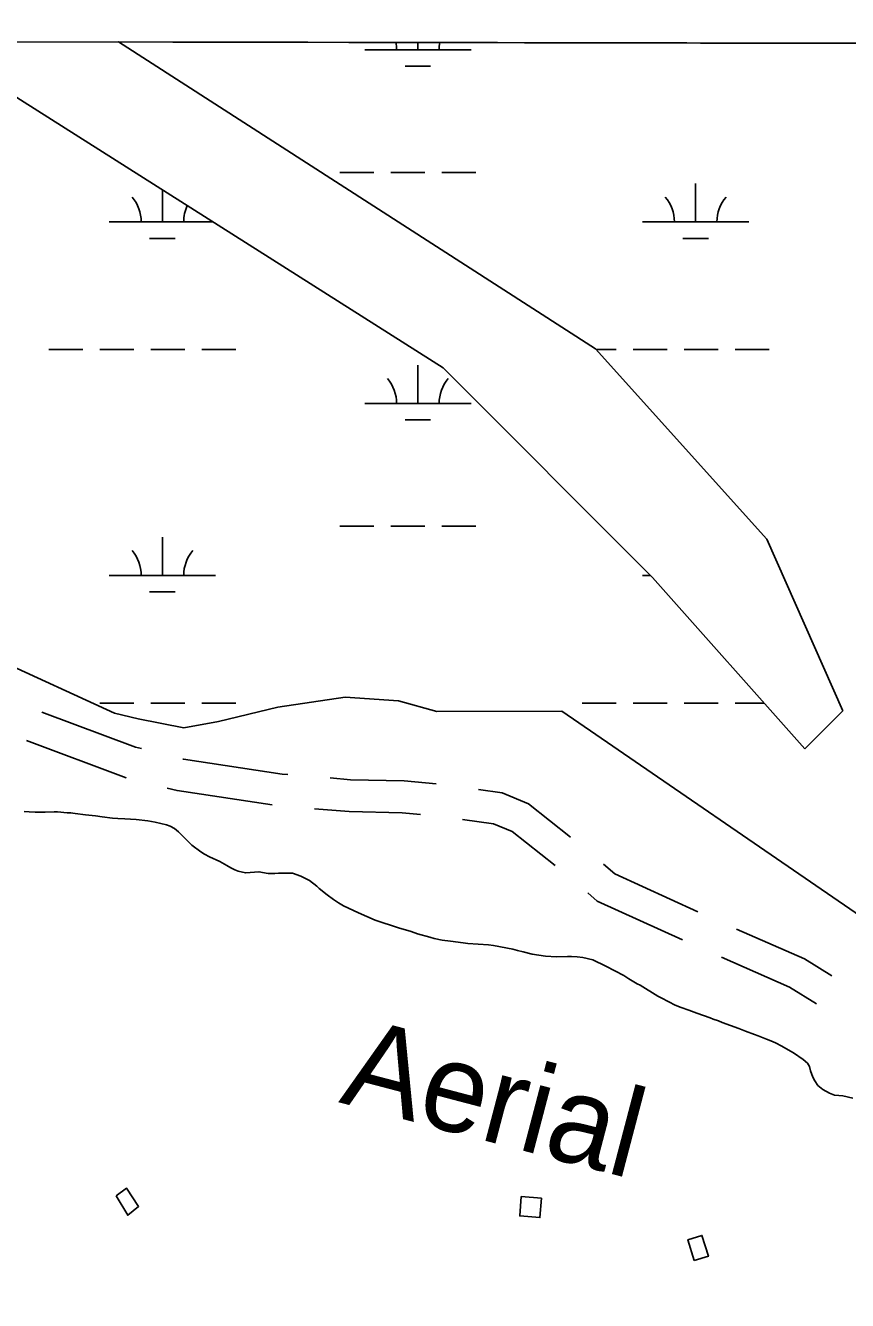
# Model space of a CAD drawing. Extents: x 3192927 to 3230760, y 831141 to 856475.
# Drawn here: x 3205224 to 3205998, y 853534 to 854733 of the extents above; entities that cross this region are included whole.
import ezdxf

# ---------------------------------------------------------------- set-up
doc = ezdxf.new("R2010")
doc.units = 0
for name, color, linetype in [('V-BLDG-OTLN', 7, 'Continuous'), ('V-GRID-FRAM', 7, 'Continuous'), ('V-RIVR-IDEN', 7, 'Continuous'), ('V-ROAD-CNTR', 7, 'Continuous'), ('V-SITE-VEGE', 7, 'Continuous'), ('V-TOPO-SHOR', 7, 'Continuous'), ('V-WETL-SWMP', 7, 'Continuous')]:
    doc.layers.add(name, color=color, linetype=linetype)

msp = doc.modelspace()

# ---------------------------------------------------------------- linework, layer by layer
at = {"layer": 'V-BLDG-OTLN'}
for points in [[(3205309.8, 853632.1), (3205319.4, 853639.3), (3205330.8, 853622), (3205320.7, 853613.8)], [(3205710.2, 853629.8), (3205708.7, 853611.6), (3205689.7, 853613.1), (3205691.1, 853631.3)], [(3205854, 853571), (3205847.9, 853590.7), (3205861.2, 853594.8), (3205867.2, 853575.1)]]:
    msp.add_lwpolyline(points, close=True, dxfattribs=at)
at = {"layer": 'V-GRID-FRAM'}
msp.add_lwpolyline([(3197144.3, 854733.3), (3228527.7, 854674), (3228501.2, 836486.7), (3197102, 836546.1), (3197144.3, 854733.3)], dxfattribs=at)
at = {"layer": 'V-ROAD-CNTR'}
for points in [[(3205239.8, 854087.3), (3205328.1, 854054.2), (3205333.7, 854052.8)], [(3205225.5, 854060.6), (3205319.1, 854025.5), (3205319.1, 854025.5)], [(3205372.4, 854042.9), (3205373, 854042.8), (3205466.1, 854028.9), (3205471.4, 854028.5)], [(3205511.2, 854025.2), (3205530.5, 854023.6), (3205580.8, 854022.5), (3205611, 854019.7)], [(3205357.9, 854015.7), (3205367.1, 854013.3), (3205456.6, 854000)], [(3205650.7, 854014.3), (3205673, 854011.2), (3205697.8, 854000.9), (3205737.5, 853969.6)], [(3205496.4, 853996.3), (3205529, 853993.7), (3205579.1, 853992.5), (3205596.2, 853990.9)], [(3205635.9, 853986.1), (3205665.1, 853982), (3205682.5, 853974.8), (3205723.1, 853942.7)], [(3205768.4, 853944.1), (3205779.1, 853934.9), (3205857.2, 853899.4)], [(3205753.8, 853917.1), (3205762.7, 853909.3), (3205843, 853872.9)], [(3205893.8, 853883.1), (3205957.6, 853854.9), (3205983.4, 853839.1)], [(3205879.5, 853856.6), (3205943.6, 853828.3), (3205969.1, 853812.7)]]:
    msp.add_lwpolyline(points, dxfattribs=at)
at = {"layer": 'V-SITE-VEGE'}
for p, q in [((3205617.6, 854411.2), (3205133.2, 854718.2)), ((3207584.8, 854713.6), (3205312.1, 854717.9)), ((3205312.1, 854717.9), (3205760.9, 854429.1)), ((3205760.9, 854429.1), (3205922.2, 854249.8)), ((3205814.7, 854213.9), (3205617.6, 854411.2)), ((3205922.2, 854249.8), (3205993.9, 854088.3)), ((3205958.1, 854052.5), (3205814.7, 854213.9)), ((3205993.9, 854088.3), (3205958.1, 854052.5)), ((3205223.3, 853993.8), (3205228, 853993.5)), ((3205228, 853993.5), (3205233.6, 853992.9)), ((3205233.6, 853992.9), (3205237.2, 853993.1)), ((3205237.2, 853993.1), (3205242.8, 853992.9)), ((3205242.8, 853992.9), (3205251.4, 853993.2)), ((3205251.4, 853993.2), (3205254.7, 853993.2)), ((3205254.7, 853993.2), (3205263.7, 853992.5)), ((3205263.7, 853992.5), (3205266.8, 853992.5)), ((3205266.8, 853992.5), (3205271.3, 853991.7)), ((3205271.3, 853991.7), (3205281, 853990.4)), ((3205281, 853990.4), (3205290.2, 853989.6)), ((3205290.2, 853989.6), (3205296.6, 853988.6)), ((3205296.6, 853988.6), (3205306.3, 853987.5)), ((3205306.3, 853987.5), (3205311.4, 853987.1)), ((3205311.4, 853987.1), (3205317.8, 853986.9)), ((3205317.8, 853986.9), (3205328.5, 853986)), ((3205328.5, 853986), (3205339.6, 853984.8)), ((3205339.6, 853984.8), (3205346.6, 853983.5)), ((3205346.6, 853983.5), (3205357, 853981.1)), ((3205357, 853981.1), (3205360.6, 853979.9)), ((3205360.6, 853979.9), (3205364.7, 853977.8)), ((3205364.7, 853977.8), (3205368.6, 853974.4)), ((3205368.6, 853974.4), (3205381, 853962.1)), ((3205381, 853962.1), (3205389.5, 853955.8)), ((3205389.5, 853955.8), (3205392.8, 853953.6)), ((3205392.8, 853953.6), (3205397.5, 853951)), ((3205397.5, 853951), (3205407.4, 853946.5)), ((3205407.4, 853946.5), (3205414, 853942.9)), ((3205414, 853942.9), (3205417.7, 853940.6)), ((3205417.7, 853940.6), (3205421.4, 853938.8)), ((3205421.4, 853938.8), (3205424.5, 853937.6)), ((3205424.5, 853937.6), (3205431.5, 853935.8)), ((3205431.5, 853935.8), (3205436, 853936.3)), ((3205436, 853936.3), (3205444.2, 853936.9)), ((3205444.2, 853936.9), (3205452.7, 853935.4)), ((3205452.7, 853935.4), (3205455.9, 853935.2)), ((3205455.9, 853935.2), (3205459.2, 853935.2)), ((3205459.2, 853935.2), (3205462.5, 853935.6)), ((3205462.5, 853935.6), (3205466.4, 853935.7)), ((3205466.4, 853935.7), (3205475.9, 853935.7)), ((3205475.9, 853935.7), (3205483.7, 853932.7)), ((3205483.7, 853932.7), (3205491.7, 853928.7)), ((3205491.7, 853928.7), (3205498.7, 853923.4)), ((3205498.7, 853923.4), (3205501, 853921.3)), ((3205501, 853921.3), (3205508.3, 853915.4)), ((3205508.3, 853915.4), (3205514.5, 853910.8)), ((3205514.5, 853910.8), (3205519.2, 853907.7)), ((3205519.2, 853907.7), (3205523.9, 853904.9)), ((3205523.9, 853904.9), (3205538, 853898.2)), ((3205538, 853898.2), (3205553.6, 853891.5)), ((3205553.6, 853891.5), (3205575.6, 853884.3)), ((3205575.6, 853884.3), (3205587.6, 853880.7)), ((3205587.6, 853880.7), (3205593.3, 853878.7)), ((3205593.3, 853878.7), (3205604.9, 853875.5)), ((3205604.9, 853875.5), (3205609.2, 853874.1)), ((3205609.2, 853874.1), (3205616.6, 853872.7)), ((3205616.6, 853872.7), (3205624.6, 853871.5)), ((3205624.6, 853871.5), (3205636.5, 853870.2)), ((3205636.5, 853870.2), (3205640.8, 853869.6)), ((3205640.8, 853869.6), (3205660.2, 853868.1)), ((3205660.2, 853868.1), (3205665.1, 853867.5)), ((3205665.1, 853867.5), (3205683.2, 853864.2)), ((3205683.2, 853864.2), (3205687.5, 853862.9)), ((3205687.5, 853862.9), (3205692.8, 853861.5)), ((3205692.8, 853861.5), (3205701.5, 853859.4)), ((3205701.5, 853859.4), (3205714, 853857.6)), ((3205714, 853857.6), (3205724.3, 853856.9)), ((3205724.3, 853856.9), (3205734.6, 853857.3)), ((3205734.6, 853857.3), (3205738.3, 853857.2)), ((3205738.3, 853857.2), (3205743.6, 853856.8)), ((3205743.6, 853856.8), (3205749.2, 853856.2)), ((3205749.2, 853856.2), (3205758.4, 853854)), ((3205758.4, 853854), (3205770.6, 853848.2)), ((3205770.6, 853848.2), (3205787.7, 853839.2)), ((3205787.7, 853839.2), (3205792.2, 853836.2)), ((3205792.2, 853836.2), (3205800.1, 853831.5)), ((3205800.1, 853831.5), (3205802.9, 853830.1)), ((3205802.9, 853830.1), (3205819.6, 853820)), ((3205819.6, 853820), (3205822.9, 853818.4)), ((3205822.9, 853818.4), (3205830, 853814.5)), ((3205830, 853814.5), (3205835.9, 853811.5)), ((3205835.9, 853811.5), (3205841.7, 853809.1)), ((3205841.7, 853809.1), (3205848.7, 853806.8)), ((3205848.7, 853806.8), (3205856.3, 853803.8)), ((3205856.3, 853803.8), (3205868.9, 853799.4)), ((3205868.9, 853799.4), (3205871.8, 853798.2)), ((3205871.8, 853798.2), (3205876.9, 853796.6)), ((3205876.9, 853796.6), (3205880.2, 853795.2)), ((3205880.2, 853795.2), (3205895.8, 853789.5)), ((3205895.8, 853789.5), (3205902.2, 853786.9)), ((3205902.2, 853786.9), (3205910.7, 853783.7)), ((3205910.7, 853783.7), (3205914, 853782.7)), ((3205914, 853782.7), (3205922, 853779.3)), ((3205922, 853779.3), (3205927.6, 853777.2)), ((3205927.6, 853777.2), (3205930.9, 853775.6)), ((3205930.9, 853775.6), (3205935.6, 853773.2)), ((3205935.6, 853773.2), (3205947.4, 853766.5)), ((3205947.4, 853766.5), (3205956.4, 853760.4)), ((3205956.4, 853760.4), (3205960.4, 853756.9)), ((3205960.4, 853756.9), (3205962.4, 853753.7)), ((3205962.4, 853753.7), (3205963.5, 853749.6)), ((3205963.5, 853749.6), (3205965.6, 853743.6)), ((3205965.6, 853743.6), (3205967.3, 853740.2)), ((3205967.3, 853740.2), (3205970.4, 853735.9)), ((3205970.4, 853735.9), (3205974.9, 853732)), ((3205974.9, 853732), (3205981.1, 853728.5)), ((3205981.1, 853728.5), (3205985.8, 853726.7)), ((3205985.8, 853726.7), (3205989.9, 853726.4)), ((3205989.9, 853726.4), (3205993.7, 853726)), ((3205993.7, 853726), (3206003.3, 853723.8))]:
    msp.add_line(p, q, dxfattribs=at)
at = {"layer": 'V-TOPO-SHOR'}
for points in [[(3205223.3, 853993.8), (3205228, 853993.5), (3205233.6, 853992.9), (3205237.2, 853993.1), (3205242.8, 853992.9), (3205251.4, 853993.2), (3205254.7, 853993.2), (3205263.7, 853992.5), (3205266.8, 853992.5), (3205271.3, 853991.7), (3205281, 853990.4), (3205290.2, 853989.6), (3205296.6, 853988.6), (3205306.3, 853987.5), (3205311.4, 853987.1), (3205317.8, 853986.9), (3205328.5, 853986), (3205339.6, 853984.8), (3205346.6, 853983.5), (3205357, 853981.1), (3205360.6, 853979.9), (3205364.7, 853977.8), (3205368.6, 853974.4), (3205381, 853962.1), (3205389.5, 853955.8), (3205392.8, 853953.6), (3205397.5, 853951), (3205407.4, 853946.5), (3205414, 853942.9), (3205417.7, 853940.6), (3205421.4, 853938.8), (3205424.5, 853937.6), (3205431.5, 853935.8), (3205436, 853936.3), (3205444.2, 853936.9), (3205452.7, 853935.4), (3205455.9, 853935.2), (3205459.2, 853935.2), (3205462.5, 853935.6), (3205466.4, 853935.7), (3205475.9, 853935.7), (3205483.7, 853932.7), (3205491.7, 853928.7), (3205498.7, 853923.4), (3205501, 853921.3), (3205508.3, 853915.4), (3205514.5, 853910.8), (3205519.2, 853907.7), (3205523.9, 853904.9), (3205538, 853898.2), (3205553.6, 853891.5), (3205575.6, 853884.3), (3205587.6, 853880.7), (3205593.3, 853878.7), (3205604.9, 853875.5), (3205609.2, 853874.1), (3205616.6, 853872.7), (3205624.6, 853871.5), (3205636.5, 853870.2), (3205640.8, 853869.6), (3205660.2, 853868.1), (3205665.1, 853867.5), (3205683.2, 853864.2), (3205687.5, 853862.9), (3205692.8, 853861.5), (3205701.5, 853859.4), (3205714, 853857.6), (3205724.3, 853856.9), (3205734.6, 853857.3), (3205738.3, 853857.2), (3205743.6, 853856.8), (3205749.2, 853856.2), (3205758.4, 853854), (3205770.6, 853848.2), (3205787.7, 853839.2), (3205792.2, 853836.2), (3205800.1, 853831.5), (3205802.9, 853830.1)], [(3205802.9, 853830.1), (3205819.6, 853820), (3205822.9, 853818.4), (3205830, 853814.5), (3205835.9, 853811.5), (3205841.7, 853809.1), (3205848.7, 853806.8), (3205856.3, 853803.8), (3205868.9, 853799.4), (3205871.8, 853798.2), (3205876.9, 853796.6), (3205880.2, 853795.2), (3205895.8, 853789.5), (3205902.2, 853786.9), (3205910.7, 853783.7), (3205914, 853782.7), (3205922, 853779.3), (3205927.6, 853777.2), (3205930.9, 853775.6), (3205935.6, 853773.2), (3205947.4, 853766.5), (3205956.4, 853760.4), (3205960.4, 853756.9), (3205962.4, 853753.7), (3205963.5, 853749.6), (3205965.6, 853743.6), (3205967.3, 853740.2), (3205970.4, 853735.9), (3205974.9, 853732), (3205981.1, 853728.5), (3205985.8, 853726.7), (3205989.9, 853726.4), (3205993.8, 853726), (3206003.3, 853723.8)]]:
    msp.add_lwpolyline(points, dxfattribs=at)
at = {"layer": 'V-WETL-SWMP'}
for p, q in [((3205617.6, 854411.2), (3205133.2, 854718.2)), ((3207150.6, 854714.4), (3205312.1, 854717.9)), ((3205312.1, 854717.9), (3205760.9, 854429.1)), ((3205543.8, 854710.3), (3205643.8, 854710.3)), ((3205593.8, 854710.3), (3205593.8, 854717.3)), ((3205581.8, 854694.9), (3205605.8, 854694.9)), ((3205520.4, 854594.9), (3205552.4, 854594.9)), ((3205568.4, 854594.9), (3205600.4, 854594.9)), ((3205616.4, 854594.9), (3205648.4, 854594.9)), ((3205353.3, 854548.5), (3205353.3, 854578.7)), ((3205855.2, 854548.5), (3205855.2, 854584.5)), ((3205303.3, 854548.5), (3205401, 854548.5)), ((3205805.2, 854548.5), (3205905.2, 854548.5)), ((3205341.3, 854533), (3205365.3, 854533)), ((3205843.2, 854533), (3205867.2, 854533)), ((3205246.5, 854428.4), (3205278.5, 854428.4)), ((3205294.5, 854428.4), (3205326.5, 854428.4)), ((3205342.5, 854428.4), (3205374.5, 854428.4)), ((3205390.5, 854428.4), (3205422.5, 854428.4)), ((3205760.9, 854429.1), (3205922.2, 854249.8)), ((3205761.6, 854428.4), (3205780.4, 854428.4)), ((3205796.4, 854428.4), (3205828.4, 854428.4)), ((3205844.4, 854428.4), (3205876.4, 854428.4)), ((3205892.4, 854428.4), (3205924.4, 854428.4)), ((3205593.8, 854377.6), (3205593.8, 854413.6)), ((3205814.7, 854213.9), (3205617.6, 854411.2)), ((3205543.8, 854377.6), (3205643.8, 854377.6)), ((3205581.8, 854362.2), (3205605.8, 854362.2)), ((3205353.3, 854215.8), (3205353.3, 854251.8)), ((3205520.4, 854262.2), (3205552.4, 854262.2)), ((3205568.4, 854262.2), (3205600.4, 854262.2)), ((3205616.4, 854262.2), (3205648.4, 854262.2)), ((3205922.2, 854249.8), (3205993.9, 854088.4)), ((3205303.3, 854215.8), (3205403.3, 854215.8)), ((3205805.2, 854215.8), (3205812.8, 854215.8)), ((3205958.1, 854052.5), (3205814.7, 854213.9)), ((3205341.3, 854200.4), (3205365.3, 854200.4)), ((3205193, 854139), (3205308.2, 854086.1)), ((3205294.5, 854095.7), (3205326.5, 854095.7)), ((3205342.5, 854095.7), (3205374.5, 854095.7)), ((3205390.5, 854095.7), (3205422.5, 854095.7)), ((3205461.8, 854091.8), (3205525.4, 854101.2)), ((3205525.4, 854101.2), (3205575.6, 854097.8)), ((3205575.6, 854097.8), (3205611.5, 854087.9)), ((3205748.4, 854095.7), (3205780.4, 854095.7)), ((3205796.4, 854095.7), (3205828.4, 854095.7)), ((3205844.4, 854095.7), (3205876.4, 854095.7)), ((3205892.4, 854095.7), (3205919.7, 854095.7)), ((3205308.2, 854086.1), (3205330.6, 854080.8)), ((3205406.2, 854078.4), (3205461.8, 854091.8)), ((3205611.5, 854087.9), (3205729.2, 854088)), ((3205729.2, 854088), (3206016.4, 853891)), ((3205993.9, 854088.4), (3205958.1, 854052.5)), ((3205330.6, 854080.8), (3205373.6, 854072.5)), ((3205373.6, 854072.5), (3205406.2, 854078.4))]:
    msp.add_line(p, q, dxfattribs=at)
for centre, start, end in [((3205538.5, 854710.8), 359.2282, 10.7406), ((3205649, 854710.8), 169.3883, 180.7718), ((3205298.1, 854548.9), 359.2282, 40.7718), ((3205408.6, 854548.9), 154.8993, 180.7718), ((3205800, 854548.9), 359.2282, 40.7718), ((3205910.5, 854548.9), 139.2282, 180.7718), ((3205538.5, 854378.1), 359.2282, 40.7718), ((3205649, 854378.1), 139.2282, 180.7718), ((3205298.1, 854216.3), 359.2282, 40.7718), ((3205408.6, 854216.3), 139.2282, 180.7718)]:
    msp.add_arc(centre, 35.2, start, end, dxfattribs=at)

# ---------------------------------------------------------------- texts
at = {"layer": 'V-RIVR-IDEN'}
msp.add_text('Aerial', height=83, rotation=345.2948, dxfattribs=at).set_placement((3205518.6, 853720.2))

doc.saveas('drawing.dxf')
